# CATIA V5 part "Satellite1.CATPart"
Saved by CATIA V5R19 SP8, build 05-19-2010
Part number: Satellite1
Bounding box of the stored display mesh (mm): x 0 to 14, y 10.311 to 50.311, z -37.5 to 2.5
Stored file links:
  G:\EU_thinkMotion\CFAO_2010\SIL_groupe2\SIL_groupe2\msauret\Brevet_Sauret_parametre\Satellite1.CATPart
  F:\Brevet_Sauret paramétré\Product3.CATProduct
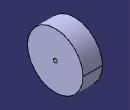
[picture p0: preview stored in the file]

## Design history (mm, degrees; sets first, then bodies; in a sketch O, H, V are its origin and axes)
Set1
  Plane1: linked copy from another document
  Point1: linked copy from another document
  Plane2: linked copy from another document
Body1 (main body)
  Sketch1 on Plane1, origin (0, 0, 0), H (0, 1, 0), V (0, 0, 1)
    circle A1 centre (30.3109, -17.5) radius 20
    point P1 (30.3109, -17.5)
    reference projected point E1 (30.3109, -17.5) from Point1
    distance P1 E1 = 0
  Pad1: profile Sketch1, direction (1, 0, 0), up to Plane2
  Sketch2 on Plane1, origin (0, 0, 0), H (0, 1, 0), V (0, 0, 1)
    circle A1 centre (30.3109, -17.5) radius 1.5
    point P1 (30.3109, -17.5)
    reference projected point E1 (30.3109, -17.5) from Point1
    distance P1 E1 = 0
  Pocket1: profile Sketch2, direction (-1, 0, 0), up to Plane2
  Plane3: type Offset, RefPlane yz-plane, Offset 9
  Sketch3 on Plane3, origin (9, 0, 0), H (0, 1, 0), V (0, 0, 1)
    circle A1 centre (30.3109, -17.5) radius 20
    point P1 (30.3109, -17.5)
    reference projected point E1 (30.3109, -17.5) from Point1
    reference projected circle E2 centre (30.3109, -17.5) radius 20 from edge [start face of Pad1 | face of Pad1 from Sketch1.A1]
    coincidence: P1 E1, A1 E2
